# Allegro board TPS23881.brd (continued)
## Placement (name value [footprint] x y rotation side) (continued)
NOREF#927  -  []  73.71 29.35 270 top
NOREF#928  -  []  53.85 71.83 90 top
NOREF#929  -  []  116.54 108.92 90 top
NOREF#930  -  []  146.25 95.33 90 top
NOREF#931  -  []  39.45 60.66 0 top
NOREF#932  -  []  151.89 120.78 90 top
NOREF#933  -  []  110.22 23.8 270 top
NOREF#934  -  []  65.41 52.25 90 top
NOREF#935  -  []  50.52 52.15 0 top
NOREF#936  -  []  31.17 30.98 90 top
NOREF#937  -  []  108.42 53.26 0 top
NOREF#938  -  []  10.13 107.65 0 top
NOREF#939  -  []  73.69 83.92 270 top
NOREF#940  -  []  42.91 36.63 270 top
NOREF#941  -  []  66.57 103.66 90 top
NOREF#942  -  []  109.72 31.37 0 top
NOREF#943  -  []  100.97 17.44 90 top
NOREF#944  -  []  47.07 26.34 0 top
NOREF#945  -  []  17.98 29.07 90 top
NOREF#946  -  []  125.65 133.43 90 top
NOREF#947  -  []  135.81 44.56 90 top
NOREF#948  -  []  35.64 192.23 0 top
NOREF#949  -  []  125.9 32.66 0 top
NOREF#950  -  []  23.06 38.9 90 top
NOREF#951  -  []  45.42 61.93 0 top
NOREF#952  -  []  137.24 45.83 90 top
NOREF#953  -  []  73.79 23.76 270 top
NOREF#954  -  []  116.33 34.43 270 top
NOREF#955  -  []  14.38 107.21 0 top
NOREF#956  -  []  43.81 125.32 270 top
NOREF#957  -  []  95.25 18.41 90 top
NOREF#958  -  []  97.92 36.59 270 top
NOREF#959  -  []  150.88 178.69 90 top
NOREF#960  -  []  118.36 18.41 90 top
NOREF#961  -  []  34.06 192.79 0 top
NOREF#962  -  []  126.44 156.29 0 top
NOREF#963  -  []  137.69 40.28 0 top
NOREF#964  -  []  37.03 17.09 90 top
NOREF#965  -  []  18.19 66.24 0 top
NOREF#966  -  []  75.01 103.17 0 top
NOREF#967  -  []  142.8 99.19 0 top
NOREF#968  -  []  47.27 34.67 0 top
NOREF#969  -  []  134.4 147.19 0 top
NOREF#970  -  []  150.19 120.47 0 top
NOREF#971  -  []  150.14 15.57 0 top
NOREF#972  -  []  100.89 95.17 90 top
NOREF#973  -  []  27.55 194.36 90 top
NOREF#974  -  []  67.03 104.09 0 top
NOREF#975  -  []  21.02 26.54 0 top
NOREF#976  -  []  156.84 176.91 0 top
NOREF#977  -  []  52.18 33.48 90 top
NOREF#978  -  []  153.19 87.88 90 top
NOREF#979  -  []  119.32 109.22 0 top
NOREF#980  -  []  111.02 128.02 0 top
NOREF#981  -  []  91.39 29.07 0 top
NOREF#982  -  []  56.16 78.16 270 top
NOREF#983  -  []  49.82 104.52 0 top
NOREF#984  -  []  135.64 17.4 90 top
NOREF#985  -  []  43.43 62.61 0 top
NOREF#986  -  []  130.63 126.29 0 top
NOREF#987  -  []  60.82 59.64 0 top
NOREF#988  -  []  132.07 54.81 90 top
NOREF#989  -  []  60.82 68.15 0 top
NOREF#990  -  []  148.79 125.81 0 top
NOREF#991  -  []  93.12 106.8 90 top
NOREF#992  -  []  38.28 177.5 90 top
NOREF#993  -  []  19.71 126.87 0 top
NOREF#994  -  []  56.46 149.3 0 top
NOREF#995  -  []  125.34 38.48 0 top
NOREF#996  -  []  43.13 18.72 0 top
NOREF#997  -  []  138.25 35.48 0 top
NOREF#998  -  []  133.6 131.28 270 top
NOREF#999  -  []  133.03 88.39 0 top
NOREF#1000  -  []  140.07 27.3 0 top
NOREF#1001  -  []  129.53 44.02 0 top
NOREF#1002  -  []  110.3 54.06 90 top
NOREF#1003  -  []  13.61 55.74 270 top
NOREF#1004  -  []  84.6 93.31 0 top
NOREF#1005  -  []  60.48 60.96 0 top
NOREF#1006  -  []  36.64 192.23 90 top
NOREF#1007  -  []  120.51 33.78 0 top
NOREF#1008  -  []  73.1 80.06 0 top
NOREF#1009  -  []  75.01 105.11 0 top
NOREF#1010  -  []  136.4 175.03 90 top
NOREF#1011  -  []  151.33 120.47 0 top
NOREF#1012  -  []  61.79 64.6 90 top
NOREF#1013  -  []  28.21 36.91 90 top
NOREF#1014  -  []  138.76 32.31 0 top
NOREF#1015  -  []  151.88 192.28 90 top
NOREF#1016  -  []  144.98 189.03 0 top
NOREF#1017  -  []  135.38 34.81 270 top
NOREF#1018  -  []  132.11 85.64 90 top
NOREF#1019  -  []  52.18 34.09 0 top
NOREF#1020  -  []  93.98 35.89 90 top
NOREF#1021  -  []  49.61 142.7 0 top
NOREF#1022  -  []  59.45 113.3 0 top
NOREF#1023  -  []  7.19 78.16 0 top
NOREF#1024  -  []  153.09 92.76 270 top
NOREF#1025  -  []  100.25 24.54 90 top
NOREF#1026  -  []  133.53 88.39 0 top
NOREF#1027  -  []  46.39 145.41 0 top
NOREF#1028  -  []  119.08 135.2 90 top
NOREF#1029  -  []  126.44 155.88 270 top
NOREF#1030  -  []  149.39 12.68 0 top
NOREF#1031  -  []  120.62 71.07 90 top
NOREF#1032  -  []  33.9 37.72 0 top
NOREF#1033  -  []  15.82 79.98 90 top
NOREF#1034  -  []  77.97 18.41 90 top
NOREF#1035  -  []  132.99 88.14 90 top
NOREF#1036  -  []  18.57 20.47 90 top
NOREF#1037  -  []  140.63 46.1 0 top
NOREF#1038  -  []  56.21 54.56 0 top
NOREF#1039  -  []  71.32 32.12 0 top
NOREF#1040  -  []  146.96 88.64 90 top
NOREF#1041  -  []  51.88 112.08 270 top
NOREF#1042  -  []  9.55 108.86 90 top
NOREF#1043  -  []  60.91 113.3 0 top
NOREF#1044  -  []  11.2 126.39 0 top
NOREF#1045  -  []  51.94 47.65 90 top
NOREF#1046  -  []  133.68 176.45 0 top
NOREF#1047  -  []  134.11 53.07 90 top
NOREF#1048  -  []  49.56 73.46 0 top
NOREF#1049  -  []  101.02 139.88 270 top
NOREF#1050  -  []  93.5 99.51 90 top
NOREF#1051  -  []  135.64 135.08 0 top
NOREF#1052  -  []  11.58 110.74 0 top
NOREF#1053  -  []  86.37 0.56 90 top
NOREF#1054  -  []  55.14 78.16 270 top
NOREF#1055  -  []  147.67 120.79 90 top
NOREF#1056  -  []  32.92 192.79 0 top
NOREF#1057  -  []  136.88 89.97 0 top
NOREF#1058  -  []  40.13 25.62 90 top
NOREF#1059  -  []  74.28 23.8 0 top
NOREF#1060  -  []  73.51 110.57 0 top
NOREF#1061  -  []  113.87 157.78 270 top
NOREF#1062  -  []  89.61 26.15 0 top
NOREF#1063  -  []  59.64 109.74 270 top
NOREF#1064  -  []  53.29 77.85 270 top
NOREF#1065  -  []  38.76 84.99 90 top
NOREF#1066  -  []  51.64 71.83 90 top
NOREF#1067  -  []  75.39 37.17 270 top
NOREF#1068  -  []  47.17 58.52 90 top
NOREF#1069  -  []  67.44 83.78 270 top
NOREF#1070  -  []  147.4 129.49 0 top
NOREF#1071  -  []  140.67 26.11 0 top
NOREF#1072  -  []  138.76 28.71 0 top
NOREF#1073  -  []  113.28 25.62 90 top
NOREF#1074  -  []  83.93 28.83 0 top
NOREF#1075  -  []  52.1 145.06 0 top
NOREF#1076  -  []  96.29 108.48 90 top
NOREF#1077  -  []  105.16 138.46 90 top
NOREF#1078  -  []  58.66 92.9 90 top
NOREF#1079  -  []  129.55 42.24 90 top
NOREF#1080  -  []  48.77 150.5 0 top
NOREF#1081  -  []  83.9 31.93 0 top
NOREF#1082  -  []  10.46 123.83 0 top
NOREF#1083  -  []  80.4 36.63 270 top
NOREF#1084  -  []  85.2 27.56 0 top
NOREF#1085  -  []  139.6 107.7 90 top
NOREF#1086  -  []  120.62 70.28 0 top
NOREF#1087  -  []  123.7 171.41 270 top
NOREF#1088  -  []  138.82 26.17 90 top
NOREF#1089  -  []  123.44 153.29 90 top
NOREF#1090  -  []  55.85 166.7 0 top
NOREF#1091  -  []  56.58 112.99 270 top
NOREF#1092  -  []  90.53 98.86 90 top
NOREF#1093  -  []  55.55 53.14 270 top
NOREF#1094  -  []  71.06 25.98 0 top
NOREF#1095  -  []  45.42 215.26 0 top
NOREF#1096  -  []  18.05 36.4 90 top
NOREF#1097  -  []  94.39 37.52 0 top
NOREF#1098  -  []  102.87 104.24 270 top
NOREF#1099  -  []  92 29.35 270 top
NOREF#1100  -  []  24.31 28.54 90 top
NOREF#1101  -  []  138.91 74.88 90 top
NOREF#1102  -  []  115.82 122.58 90 top
NOREF#1103  -  []  146.05 121.79 270 top
NOREF#1104  -  []  37.36 105.44 0 top
NOREF#1105  -  []  127.69 56.52 0 top
NOREF#1106  -  []  95.52 101.83 90 top
NOREF#1107  -  []  37.07 25.22 0 top
NOREF#1108  -  []  133.48 42.28 90 top
NOREF#1109  -  []  142.82 127.69 0 top
NOREF#1110  -  []  57.34 112.95 270 top
NOREF#1111  -  []  145.16 134.09 270 top
NOREF#1112  -  []  82.31 34.52 270 top
NOREF#1113  -  []  134.37 146.94 0 top
NOREF#1114  -  []  144.98 105.23 0 top
NOREF#1115  -  []  58.99 91.68 0 top
NOREF#1116  -  []  55.4 167.13 0 top
NOREF#1117  -  []  43.43 62.1 90 top
NOREF#1118  -  []  15.52 108.74 0 top
NOREF#1119  -  []  39.99 25.58 90 top
NOREF#1120  -  []  19.76 70.82 0 top
NOREF#1121  -  []  17.98 35.04 90 top
NOREF#1122  -  []  91.94 25.22 0 top
NOREF#1123  -  []  98.73 139.88 270 top
NOREF#1124  -  []  138.76 29.96 0 top
NOREF#1125  -  []  107.9 28.33 270 top
NOREF#1126  -  []  47.93 33.64 90 top
NOREF#1127  -  []  73.65 25.22 0 top
NOREF#1128  -  []  94.51 101.83 0 top
NOREF#1129  -  []  27.04 37.39 0 top
NOREF#1130  -  []  128.92 42.24 90 top
NOREF#1131  -  []  117.73 35.97 90 top
NOREF#1132  -  []  157.77 112.2 90 top
NOREF#1133  -  []  136.89 27.99 0 top
NOREF#1134  -  []  121.62 182.04 0 top
NOREF#1135  -  []  70.94 29.98 270 top
NOREF#1136  -  []  137.11 87.96 90 top
NOREF#1137  -  []  128.98 72.95 270 top
NOREF#1138  -  []  119.39 180.47 90 top
NOREF#1139  -  []  58.88 73.19 270 top
NOREF#1140  -  []  135.17 40.06 90 top
NOREF#1141  -  []  43 65.48 0 top
NOREF#1142  -  []  89.65 28.83 0 top
NOREF#1143  -  []  139.34 40.67 90 top
NOREF#1144  -  []  156.99 9.7 90 top
NOREF#1145  -  []  138.33 42.8 0 top
NOREF#1146  -  []  21.03 21.79 90 top
NOREF#1147  -  []  19.76 71.96 0 top
NOREF#1148  -  []  20.43 39.19 0 top
NOREF#1149  -  []  108.58 155.83 0 top
NOREF#1150  -  []  72.72 53.54 90 top
NOREF#1151  -  []  51.61 102.57 0 top
NOREF#1152  -  []  51.1 104.83 270 top
NOREF#1153  -  []  6.3 84.18 90 top
NOREF#1154  -  []  137.27 45.97 0 top
NOREF#1155  -  []  138.48 89.03 0 top
NOREF#1156  -  []  75.46 106.17 0 top
NOREF#1157  -  []  45.72 60.58 90 top
NOREF#1158  -  []  31.75 12.52 270 top
NOREF#1159  -  []  54.31 148.89 270 top
NOREF#1160  -  []  38.51 101.73 0 top
NOREF#1161  -  []  128.52 173.99 90 top
NOREF#1162  -  []  70.33 141.43 0 top
NOREF#1163  -  []  109.91 35.51 90 top
NOREF#1164  -  []  103.36 51.83 90 top
NOREF#1165  -  []  94.12 99.43 90 top
NOREF#1166  -  []  89.31 108.84 0 top
NOREF#1167  -  []  117.3 35.51 0 top
NOREF#1168  -  []  142.88 70.57 270 top
NOREF#1169  -  []  52.32 33.52 90 top
NOREF#1170  -  []  38.56 36.2 90 top
NOREF#1171  -  []  132.36 56.29 90 top
NOREF#1172  -  []  60.87 69.22 0 top
NOREF#1173  -  []  134.52 56.29 0 top
NOREF#1174  -  []  71.39 33.48 90 top
NOREF#1175  -  []  83.64 51.38 90 top
NOREF#1176  -  []  69.77 151.59 90 top
NOREF#1177  -  []  121.34 44.58 0 top
NOREF#1178  -  []  137.24 102.95 0 top
NOREF#1179  -  []  108.71 12.52 0 top
NOREF#1180  -  []  61.4 91.68 0 top
NOREF#1181  -  []  115.72 43.28 0 top
NOREF#1182  -  []  70.94 29.71 0 top
NOREF#1183  -  []  90.87 99.16 0 top
NOREF#1184  -  []  132.7 56.59 0 top
NOREF#1185  -  []  60.82 64.85 0 top
NOREF#1186  -  []  114.3 -29.84 0 top
NOREF#1187  -  []  11.89 123.39 90 top
NOREF#1188  -  []  124.21 17.44 90 top
NOREF#1189  -  []  128.51 24.18 270 top
NOREF#1190  -  []  47.07 186.64 90 top
NOREF#1191  -  []  89.32 32.28 0 top
NOREF#1192  -  []  45.2 45.67 0 top
NOREF#1193  -  []  53.85 73.46 0 top
NOREF#1194  -  []  21.13 126.44 90 top
NOREF#1195  -  []  84.2 51.08 90 top
NOREF#1196  -  []  20.71 28.18 90 top
NOREF#1197  -  []  19.13 20.78 90 top
NOREF#1198  -  []  150.91 192.53 0 top
NOREF#1199  -  []  62.1 63.12 270 top
NOREF#1200  -  []  85.91 54.61 90 top
NOREF#1201  -  []  57.26 91.53 270 top
NOREF#1202  -  []  63.74 27.61 0 top
NOREF#1203  -  []  135.41 104.52 0 top
NOREF#1204  -  []  85.04 103.68 270 top
NOREF#1205  -  []  141.33 75.85 270 top
NOREF#1206  -  []  102.23 32.16 90 top
NOREF#1207  -  []  124.21 181.74 270 top
NOREF#1208  -  []  1.27 179.83 0 top
NOREF#1209  -  []  115.04 84.53 90 top
NOREF#1210  -  []  120.09 31.7 90 top
NOREF#1211  -  []  68.83 174.08 270 top
NOREF#1212  -  []  46.37 0.56 90 top
NOREF#1213  -  []  55.75 173.86 90 top
NOREF#1214  -  []  140.03 133.78 0 top
NOREF#1215  -  []  98.4 102.16 0 top
NOREF#1216  -  []  151.59 147.65 0 top
NOREF#1217  -  []  83.95 31.62 270 top
NOREF#1218  -  []  29.55 197.56 90 top
NOREF#1219  -  []  67.69 57.4 270 top
NOREF#1220  -  []  142.19 136.32 0 top
NOREF#1221  -  []  38.8 95.97 90 top
NOREF#1222  -  []  46.02 29.35 270 top
NOREF#1223  -  []  49.35 107.24 270 top
NOREF#1224  -  []  45.42 27.47 0 top
NOREF#1225  -  []  145.16 120.68 90 top
NOREF#1226  -  []  65.63 156.54 0 top
NOREF#1227  -  []  142.82 102.95 0 top
NOREF#1228  -  []  137.54 127.61 270 top
NOREF#1229  -  []  147.96 129.79 90 top
NOREF#1230  -  []  60.78 62.56 0 top
NOREF#1231  -  []  12.55 118.82 0 top
NOREF#1232  -  []  131.43 25.96 0 top
NOREF#1233  -  []  123.7 154.27 270 top
NOREF#1234  -  []  19.76 72.82 270 top
NOREF#1235  -  []  75.46 101.85 0 top
NOREF#1236  -  []  150.91 180.09 0 top
NOREF#1237  -  []  52.7 32.42 0 top
NOREF#1238  -  []  26.42 37.35 270 top
NOREF#1239  -  []  115.76 25.58 90 top
NOREF#1240  -  []  127.03 177.52 0 top
NOREF#1241  -  []  51.64 58.24 270 top
NOREF#1242  -  []  66.88 27.42 0 top
NOREF#1243  -  []  61.46 112.98 90 top
NOREF#1244  -  []  61.19 181.53 0 top
NOREF#1245  -  []  27.88 28.61 90 top
NOREF#1246  -  []  64.1 91.07 90 top
NOREF#1247  -  []  47.36 145.16 90 top
NOREF#1248  -  []  126.7 139.62 270 top
NOREF#1249  -  []  16.92 106.58 90 top
NOREF#1250  -  []  99.81 64.65 90 top
NOREF#1251  -  []  65.1 67.49 270 top
NOREF#1252  -  []  92.06 36.27 0 top
NOREF#1253  -  []  132.03 121.97 0 top
NOREF#1254  -  []  61.34 36.06 90 top
NOREF#1255  -  []  134.92 131.62 270 top
NOREF#1256  -  []  50.11 72.14 90 top
NOREF#1257  -  []  36.56 27.3 0 top
NOREF#1258  -  []  40.96 25.58 90 top
NOREF#1259  -  []  67.81 89.52 0 top
NOREF#1260  -  []  130.63 160.1 0 top
NOREF#1261  -  []  146.43 134.09 270 top
NOREF#1262  -  []  138.94 30.33 270 top
NOREF#1263  -  []  126.44 154.61 270 top
NOREF#1264  -  []  129.27 55.42 0 top
NOREF#1265  -  []  18.59 30.34 90 top
NOREF#1266  -  []  107.9 26.43 270 top
NOREF#1267  -  []  146.81 95.63 90 top
NOREF#1268  -  []  131.02 37.58 90 top
NOREF#1269  -  []  136.94 139.83 0 top
NOREF#1270  -  []  125.4 72.31 270 top
NOREF#1271  -  []  95.96 25.62 90 top
NOREF#1272  -  []  30.59 31.75 0 top
NOREF#1273  -  []  17.98 31.61 0 top
NOREF#1274  -  []  63.63 17.44 90 top
NOREF#1275  -  []  131.83 52.95 90 top
NOREF#1276  -  []  136.14 56.29 90 top
NOREF#1277  -  []  113.08 159.46 90 top
NOREF#1278  -  []  57.48 56.97 0 top
NOREF#1279  -  []  60.48 63.12 0 top
NOREF#1280  -  []  73.25 82.5 0 top
NOREF#1281  -  []  148.54 129.49 0 top
NOREF#1282  -  []  57.87 37.2 90 top
NOREF#1283  -  []  142.34 99.62 0 top
NOREF#1284  -  []  60 112.98 90 top
NOREF#1285  -  []  137.67 121.53 90 top
NOREF#1286  -  []  87.96 92.51 270 top
NOREF#1287  -  []  70.94 28.05 0 top
NOREF#1288  -  []  74.14 194.39 90 top
NOREF#1289  -  []  116.23 70.46 270 top
NOREF#1290  -  []  131.9 158.29 270 top
NOREF#1291  -  []  55.7 77.85 270 top
NOREF#1292  -  []  26.56 37.39 270 top
NOREF#1293  -  []  56.26 36.84 270 top
NOREF#1294  -  []  126.19 30.72 0 top
NOREF#1295  -  []  120.56 26.04 0 top
NOREF#1296  -  []  97.52 51.83 90 top
NOREF#1297  -  []  131.32 176.91 90 top
NOREF#1298  -  []  66.84 101.05 270 top
NOREF#1299  -  []  68.83 25.78 90 top
NOREF#1300  -  []  108.62 155.57 0 top
NOREF#1301  -  []  89.61 30.34 0 top
NOREF#1302  -  []  17.98 34.4 0 top
NOREF#1303  -  []  60.73 71.88 0 top
NOREF#1304  -  []  70.85 36.63 270 top
NOREF#1305  -  []  18.02 32.77 0 top
NOREF#1306  -  []  58.99 112.98 90 top
NOREF#1307  -  []  12.22 80.54 0 top
NOREF#1308  -  []  132.97 175.04 90 top
NOREF#1309  -  []  144.83 127.69 270 top
NOREF#1310  -  []  149.17 66.85 270 top
NOREF#1311  -  []  71.32 32.4 270 top
NOREF#1312  -  []  153.09 90.47 270 top
NOREF#1313  -  []  6.93 108.41 90 top
NOREF#1314  -  []  53.2 33.65 90 top
NOREF#1315  -  []  120.65 134.47 270 top
NOREF#1316  -  []  149.66 68.96 0 top
NOREF#1317  -  []  28.63 29.34 0 top
NOREF#1318  -  []  58.48 95.85 270 top
NOREF#1319  -  []  52.55 194.36 90 top
NOREF#1320  -  []  17.98 80 90 top
NOREF#1321  -  []  96.33 95.25 0 top
NOREF#1322  -  []  43.69 17.4 90 top
NOREF#1323  -  []  125.02 51.04 90 top
NOREF#1324  -  []  83.93 28.19 0 top
NOREF#1325  -  []  144.86 181.15 0 top
NOREF#1326  -  []  23.28 28.49 90 top
NOREF#1327  -  []  132.36 56.9 0 top
NOREF#1328  -  []  16.54 79.53 90 top
NOREF#1329  -  []  100.25 26.42 0 top
NOREF#1330  -  []  89.61 32.4 270 top
NOREF#1331  -  []  142.57 122.15 0 top
NOREF#1332  -  []  148.59 193.8 90 top
NOREF#1333  -  []  140.59 50.8 0 top
NOREF#1334  -  []  95.12 109.45 270 top
NOREF#1335  -  []  138.38 177.46 0 top
NOREF#1336  -  []  45.72 63.25 90 top
NOREF#1337  -  []  49.57 26.04 0 top
NOREF#1338  -  []  62.23 112.95 270 top
NOREF#1339  -  []  138.8 34.16 0 top
NOREF#1340  -  []  60.02 72.25 90 top
NOREF#1341  -  []  128.75 42.48 270 top
NOREF#1342  -  []  140.87 150.6 0 top
NOREF#1343  -  []  100.46 94.72 90 top
NOREF#1344  -  []  59.23 73.33 270 top
NOREF#1345  -  []  54.81 109.87 0 top
NOREF#1346  -  []  9.98 109.32 90 top
NOREF#1347  -  []  49.35 108.38 0 top
NOREF#1348  -  []  134.06 146.35 0 top
NOREF#1349  -  []  121.23 76.4 90 top
NOREF#1350  -  []  44.73 47.37 0 top
NOREF#1351  -  []  146.57 109.66 270 top
NOREF#1352  -  []  62.1 59.33 90 top
NOREF#1353  -  []  115.19 17.44 90 top
NOREF#1354  -  []  39.12 35.89 90 top
NOREF#1355  -  []  132.4 25.96 90 top
NOREF#1356  -  []  131.78 94.16 0 top
NOREF#1357  -  []  56.32 112.95 270 top
NOREF#1358  -  []  100.66 18.72 0 top
NOREF#1359  -  []  124.41 42.41 0 top
NOREF#1360  -  []  57.71 170.89 90 top
NOREF#1361  -  []  135.23 87.43 0 top
NOREF#1362  -  []  76.57 25.58 0 top
NOREF#1363  -  []  52.22 143.13 0 top
NOREF#1364  -  []  149.2 71.2 0 top
NOREF#1365  -  []  38.51 93.22 0 top
NOREF#1366  -  []  54.53 56.31 270 top
NOREF#1367  -  []  56.64 75.65 270 top
NOREF#1368  -  []  92.43 109.4 0 top
NOREF#1369  -  []  21.03 20.78 90 top
NOREF#1370  -  []  68.15 82.5 0 top
NOREF#1371  -  []  30.61 28.7 0 top
NOREF#1372  -  []  140.28 45.8 90 top
NOREF#1373  -  []  146.81 112.65 0 top
NOREF#1374  -  []  16.71 108.92 90 top
NOREF#1375  -  []  45.16 45.42 90 top
NOREF#1376  -  []  148.51 127.69 270 top
NOREF#1377  -  []  39.45 66.75 0 top
NOREF#1378  -  []  35.03 31.79 270 top
NOREF#1379  -  []  126.99 41.53 0 top
NOREF#1380  -  []  47.96 141.15 270 top
NOREF#1381  -  []  107.94 27.56 0 top
NOREF#1382  -  []  62.1 65.15 270 top
NOREF#1383  -  []  93.98 23.76 270 top
NOREF#1384  -  []  137.69 103.38 0 top
NOREF#1385  -  []  138.81 121.79 270 top
NOREF#1386  -  []  110.03 70.11 90 top
NOREF#1387  -  []  70.94 28.69 0 top
NOREF#1388  -  []  69.19 83.62 90 top
NOREF#1389  -  []  84.48 109.6 90 top
NOREF#1390  -  []  32.92 193.07 0 top
NOREF#1391  -  []  141.6 149.52 90 top
NOREF#1392  -  []  66.88 27.7 270 top
NOREF#1393  -  []  57.4 23.76 270 top
NOREF#1394  -  []  54.1 55.85 270 top
NOREF#1395  -  []  47.93 28.05 90 top
NOREF#1396  -  []  57.59 112.99 270 top
NOREF#1397  -  []  50.44 53.11 90 top
NOREF#1398  -  []  35.64 17.09 90 top
NOREF#1399  -  []  74.65 53.54 0 top
NOREF#1400  -  []  106.78 154.76 0 top
NOREF#1401  -  []  134.37 144.66 90 top
NOREF#1402  -  []  126.35 37.01 270 top
NOREF#1403  -  []  47.07 28.52 0 top
NOREF#1404  -  []  17.69 34.57 0 top
NOREF#1405  -  []  18.24 79.96 90 top
NOREF#1406  -  []  129.41 65.43 90 top
NOREF#1407  -  []  56.34 76 0 top
NOREF#1408  -  []  89.32 31.65 0 top
NOREF#1409  -  []  122.89 182.04 0 top
NOREF#1410  -  []  98.5 65.2 0 top
NOREF#1411  -  []  152.53 136.14 90 top
NOREF#1412  -  []  150.57 192.84 0 top
NOREF#1413  -  []  109.68 31.23 90 top
NOREF#1414  -  []  143.26 126.26 90 top
NOREF#1415  -  []  150.57 180.39 270 top
NOREF#1416  -  []  36.83 127.86 270 top
NOREF#1417  -  []  63.7 26.71 0 top
NOREF#1418  -  []  73.18 56.03 0 top
NOREF#1419  -  []  71.03 31.65 0 top
NOREF#1420  -  []  140.11 107.7 90 top
NOREF#1421  -  []  82.03 26.85 0 top
NOREF#1422  -  []  91.94 25.22 90 top
NOREF#1423  -  []  110.82 138.25 90 top
NOREF#1424  -  []  38.96 91.64 0 top
NOREF#1425  -  []  125.22 136.55 90 top
NOREF#1426  -  []  54.1 58.25 270 top
NOREF#1427  -  []  75.01 102.03 0 top
NOREF#1428  -  []  126.44 159.56 0 top
NOREF#1429  -  []  123.95 171.45 270 top
NOREF#1430  -  []  65.56 68.2 0 top
NOREF#1431  -  []  134.37 148.21 90 top
NOREF#1432  -  []  85.04 103.68 0 top
NOREF#1433  -  []  63.61 51.58 90 top
NOREF#1434  -  []  111.81 151.76 0 top
NOREF#1435  -  []  143.75 93.52 0 top
NOREF#1436  -  []  149.1 129.79 90 top
NOREF#1437  -  []  84.87 2.26 90 top
NOREF#1438  -  []  57.78 17.4 90 top
NOREF#1439  -  []  131.98 155.45 0 top
NOREF#1440  -  []  154.97 114.31 90 top
NOREF#1441  -  []  19.76 33.74 0 top
NOREF#1442  -  []  133.91 131.62 270 top
NOREF#1443  -  []  150.67 115.57 0 top
NOREF#1444  -  []  134.62 131.28 270 top
NOREF#1445  -  []  134.37 145.8 90 top
NOREF#1446  -  []  55.37 82.63 0 top
NOREF#1447  -  []  68.33 12.52 0 top
NOREF#1448  -  []  74.98 80.06 270 top
NOREF#1449  -  []  134.85 88.09 90 top
NOREF#1450  -  []  140.89 179.37 270 top
NOREF#1451  -  []  134.8 134.7 90 top
NOREF#1452  -  []  115.87 88.14 0 top
NOREF#1453  -  []  100.13 64.59 90 top
NOREF#1454  -  []  19.8 29.46 0 top
NOREF#1455  -  []  98.84 65.91 0 top
NOREF#1456  -  []  136.53 64.52 90 top
NOREF#1457  -  []  54.81 30.47 90 top
NOREF#1458  -  []  45.39 26.42 0 top
NOREF#1459  -  []  46.02 26.99 270 top
NOREF#1460  -  []  137.03 76.07 0 top
NOREF#1461  -  []  102.18 33.92 0 top
NOREF#1462  -  []  114.94 133.99 90 top
NOREF#1463  -  []  47.71 112.08 270 top
NOREF#1464  -  []  18.8 180.59 0 top
NOREF#1465  -  []  75.46 101.6 0 top
NOREF#1466  -  []  137.03 75.06 0 top
NOREF#1467  -  []  124.08 45.92 0 top
NOREF#1468  -  []  61.47 33.9 90 top
NOREF#1469  -  []  58.57 84.25 270 top
NOREF#1470  -  []  70.79 143.89 0 top
NOREF#1471  -  []  56.29 171.32 0 top
NOREF#1472  -  []  47.96 138.86 0 top
NOREF#1473  -  []  49.2 26.78 90 top
NOREF#1474  -  []  89.61 27.7 0 top
NOREF#1475  -  []  131.84 44.63 270 top
NOREF#1476  -  []  65.84 80.42 0 top
NOREF#1477  -  []  141.01 26.42 0 top
NOREF#1478  -  []  65.1 35.1 0 top
NOREF#1479  -  []  60.27 17.09 90 top
NOREF#1480  -  []  73.25 82.5 0 top
NOREF#1481  -  []  127.04 139.32 0 top
NOREF#1482  -  []  149.66 70.1 0 top
NOREF#1483  -  []  62.98 34.52 0 top
NOREF#1484  -  []  108.03 60.04 90 top
NOREF#1485  -  []  62.94 188.16 0 top
NOREF#1486  -  []  156.81 113.65 90 top
NOREF#1487  -  []  106.55 33.52 90 top
NOREF#1488  -  []  81.86 35.51 90 top
NOREF#1489  -  []  140.09 176.41 0 top
NOREF#1490  -  []  107.9 26.15 0 top
NOREF#1491  -  []  152.04 151.89 0 top
NOREF#1492  -  []  60.48 68.45 0 top
NOREF#1493  -  []  113.14 25.58 90 top
NOREF#1494  -  []  12.75 106.12 90 top
NOREF#1495  -  []  76.71 26.15 270 top
NOREF#1496  -  []  138.42 177.32 0 top
NOREF#1497  -  []  28.02 28.65 90 top
NOREF#1498  -  []  149.05 150.32 90 top
NOREF#1499  -  []  38.98 23.8 0 top
NOREF#1500  -  []  28.6 54.14 90 top
NOREF#1501  -  []  54.74 151 0 top
NOREF#1502  -  []  27.06 38.94 90 top
NOREF#1503  -  []  127.23 56.95 270 top
NOREF#1504  -  []  61.04 51.38 90 top
NOREF#1505  -  []  54.61 168.69 90 top
NOREF#1506  -  []  19.38 79.96 90 top
NOREF#1507  -  []  107.94 32.26 0 top
NOREF#1508  -  []  52.96 55.85 270 top
NOREF#1509  -  []  58.29 109.47 270 top
NOREF#1510  -  []  132.7 55.42 0 top
NOREF#1511  -  []  124.28 65.23 0 top
NOREF#1512  -  []  41.72 25.58 0 top
NOREF#1513  -  []  146.13 173.66 270 top
NOREF#1514  -  []  72.14 6.93 90 top
NOREF#1515  -  []  76.33 52.58 270 top
NOREF#1516  -  []  111.66 37.52 0 top
NOREF#1517  -  []  149.68 99.01 90 top
NOREF#1518  -  []  17.3 114.58 90 top
NOREF#1519  -  []  137.24 46.47 90 top
NOREF#1520  -  []  139.78 43.51 90 top
NOREF#1521  -  []  58.74 112.95 270 top
NOREF#1522  -  []  103.45 27.7 270 top
NOREF#1523  -  []  115.42 87.71 90 top
NOREF#1524  -  []  8.38 110.52 90 top
NOREF#1525  -  []  146.13 128.09 90 top
NOREF#1526  -  []  63.27 177.04 0 top
NOREF#1527  -  []  48.41 139.57 0 top
NOREF#1528  -  []  92.02 60.87 270 top
NOREF#1529  -  []  43.32 34.47 270 top
NOREF#1530  -  []  9.86 79.58 90 top
NOREF#1531  -  []  73.1 30.75 270 top
NOREF#1532  -  []  147.57 134.09 270 top
NOREF#1533  -  []  136.73 76.63 0 top
NOREF#1534  -  []  65.2 80.37 0 top
NOREF#1535  -  []  102.22 33.78 0 top
NOREF#1536  -  []  128.02 165.82 270 top
NOREF#1537  -  []  134.62 52.88 0 top
NOREF#1538  -  []  125.09 76.86 90 top
NOREF#1539  -  []  125.34 34.47 270 top
NOREF#1540  -  []  43.43 17.44 90 top
NOREF#1541  -  []  18.82 79.65 0 top
NOREF#1542  -  []  22.94 20.78 90 top
NOREF#1543  -  []  39.9 64.64 0 top
NOREF#1544  -  []  131.27 176.61 0 top
NOREF#1545  -  []  147.8 99.01 0 top
NOREF#1546  -  []  61.93 113.3 270 top
NOREF#1547  -  []  129.62 55.12 0 top
NOREF#1548  -  []  128.73 139.75 0 top
NOREF#1549  -  []  152.55 19.71 0 top
NOREF#1550  -  []  126.95 41.39 0 top
NOREF#1551  -  []  151.52 101.85 270 top
NOREF#1552  -  []  127.97 30.85 90 top
NOREF#1553  -  []  29.5 191.26 0 top
NOREF#1554  -  []  96.22 18.72 0 top
NOREF#1555  -  []  145.43 109.66 270 top
NOREF#1556  -  []  119.08 133.05 0 top
NOREF#1557  -  []  116.48 39.24 90 top
NOREF#1558  -  []  109.68 30.75 0 top
NOREF#1559  -  []  57.33 151.18 270 top
NOREF#1560  -  []  73.14 31.37 0 top
NOREF#1561  -  []  15.31 21.79 90 top
NOREF#1562  -  []  109.91 152.86 90 top
NOREF#1563  -  []  9.44 109.6 90 top
NOREF#1564  -  []  70.94 28.33 270 top
NOREF#1565  -  []  17.13 40.64 0 top
NOREF#1566  -  []  135.15 88.65 0 top
NOREF#1567  -  []  150.91 177.8 0 top
NOREF#1568  -  []  149.17 74.75 270 top
NOREF#1569  -  []  101.93 25.73 90 top
NOREF#1570  -  []  61.49 181.88 90 top
NOREF#1571  -  []  131.09 72.39 90 top
NOREF#1572  -  []  46.89 76.07 0 top
NOREF#1573  -  []  60.01 25.58 90 top
NOREF#1574  -  []  63.58 35.51 0 top
NOREF#1575  -  []  126.24 77.83 270 top
NOREF#1576  -  []  135.27 36.4 90 top
NOREF#1577  -  []  50.44 98.45 0 top
NOREF#1578  -  []  123.77 45.87 90 top
NOREF#1579  -  []  33.35 191.36 90 top
NOREF#1580  -  []  73.79 25.79 270 top
NOREF#1581  -  []  76.89 104.32 270 top
NOREF#1582  -  []  137.04 75.06 90 top
NOREF#1583  -  []  97.47 25.58 0 top
NOREF#1584  -  []  65.13 66.34 0 top
NOREF#1585  -  []  150.6 149.83 0 top
NOREF#1586  -  []  70.33 83.36 270 top
NOREF#1587  -  []  110.86 23.8 0 top
NOREF#1588  -  []  150.14 17.5 270 top
NOREF#1589  -  []  133.46 44.63 0 top
NOREF#1590  -  []  131.04 73.71 270 top
NOREF#1591  -  []  65.1 35.1 270 top
NOREF#1592  -  []  25.4 65.44 0 top
NOREF#1593  -  []  140.59 79.24 90 top
NOREF#1594  -  []  18.29 109.22 90 top
NOREF#1595  -  []  45.8 70.14 270 top
NOREF#1596  -  []  139.55 107.39 0 top
NOREF#1597  -  []  98.42 95.51 90 top
NOREF#1598  -  []  116.2 36.59 270 top
NOREF#1599  -  []  49.15 58.24 270 top
NOREF#1600  -  []  47.36 28.83 0 top
NOREF#1601  -  []  128 54.69 90 top
NOREF#1602  -  []  32.92 190.91 90 top
NOREF#1603  -  []  35.89 37.39 0 top
NOREF#1604  -  []  107.01 38.24 0 top
NOREF#1605  -  []  139.78 40.21 90 top
NOREF#1606  -  []  126.9 155.45 0 top
NOREF#1607  -  []  70.98 28.19 0 top
NOREF#1608  -  []  75.05 18.41 90 top
NOREF#1609  -  []  132.84 54.85 90 top
NOREF#1610  -  []  13.46 106.58 90 top
NOREF#1611  -  []  137.04 76.08 90 top
NOREF#1612  -  []  10.52 72.97 0 top
NOREF#1613  -  []  91.92 102.51 0 top
NOREF#1614  -  []  164.19 74.63 0 top
NOREF#1615  -  []  101.73 109.07 270 top
NOREF#1616  -  []  39.88 108.74 90 top
NOREF#1617  -  []  83.52 31.7 90 top
NOREF#1618  -  []  127.64 73.66 0 top
NOREF#1619  -  []  58.7 166.75 0 top
NOREF#1620  -  []  54.81 31.23 90 top
NOREF#1621  -  []  46 139.57 0 top
NOREF#1622  -  []  52.7 58.29 270 top
NOREF#1623  -  []  87.4 92.2 270 top
NOREF#1624  -  []  75.55 23.8 270 top
NOREF#1625  -  []  124.16 182.04 0 top
NOREF#1626  -  []  111.2 158.32 0 top
NOREF#1627  -  []  151.64 121.75 270 top
NOREF#1628  -  []  92.71 23.76 270 top
NOREF#1629  -  []  11.89 106.12 0 top
NOREF#1630  -  []  17.51 39.55 0 top
NOREF#1631  -  []  123.39 171.75 270 top
NOREF#1632  -  []  66.84 94.45 0 top
NOREF#1633  -  []  49.17 96.52 270 top
NOREF#1634  -  []  134.37 149.22 0 top
NOREF#1635  -  []  132.92 134.7 0 top
NOREF#1636  -  []  137.31 89.51 270 top
NOREF#1637  -  []  88.85 109.27 270 top
NOREF#1638  -  []  146.81 129.79 90 top
NOREF#1639  -  []  17.09 40.78 270 top
NOREF#1640  -  []  30.55 32.5 0 top
NOREF#1641  -  []  104.09 25.73 0 top
NOREF#1642  -  []  36.56 29.21 0 top
NOREF#1643  -  []  62.94 188.16 0 top
NOREF#1644  -  []  56.34 76 270 top
NOREF#1645  -  []  80.26 36.59 270 top
NOREF#1646  -  []  127.18 140.03 90 top
NOREF#1647  -  []  39.99 25.58 0 top
NOREF#1648  -  []  65.75 91.07 90 top
NOREF#1649  -  []  136.22 64.47 90 top
NOREF#1650  -  []  143.66 100.05 270 top
NOREF#1651  -  []  63.74 26.85 0 top
NOREF#1652  -  []  138.76 34.3 0 top
NOREF#1653  -  []  20.71 28.18 0 top
NOREF#1654  -  []  51.64 173.61 0 top
NOREF#1655  -  []  89.14 36.63 270 top
NOREF#1656  -  []  149.43 134.54 0 top
NOREF#1657  -  []  126.61 52.32 0 top
NOREF#1658  -  []  120.51 29.72 0 top
NOREF#1659  -  []  37.8 104.47 0 top
NOREF#1660  -  []  89.61 26.43 270 top
NOREF#1661  -  []  73.1 76.78 0 top
NOREF#1662  -  []  102.22 32.51 0 top
NOREF#1663  -  []  126.23 29.21 0 top
NOREF#1664  -  []  141.29 62.36 0 top
NOREF#1665  -  []  127.48 65.04 0 top
NOREF#1666  -  []  125.72 37.01 0 top
NOREF#1667  -  []  21.65 25.93 90 top
NOREF#1668  -  []  49.83 138.86 270 top
NOREF#1669  -  []  141.48 175.51 0 top
NOREF#1670  -  []  45.67 138.13 0 top
NOREF#1671  -  []  115.39 119.33 90 top
NOREF#1672  -  []  114.91 109.52 0 top
NOREF#1673  -  []  120.22 28.52 0 top
NOREF#1674  -  []  75.97 85.7 270 top
NOREF#1675  -  []  88.85 106.22 270 top
NOREF#1676  -  []  93.5 191.13 0 top
NOREF#1677  -  []  94.59 102.95 0 top
NOREF#1678  -  []  93.07 107.11 0 top
NOREF#1679  -  []  70.33 81.48 0 top
NOREF#1680  -  []  146.3 95.63 90 top
NOREF#1681  -  []  36.56 30.61 0 top
NOREF#1682  -  []  134.87 130.3 90 top
NOREF#1683  -  []  120.51 32.51 0 top
NOREF#1684  -  []  139.37 184.45 270 top
NOREF#1685  -  []  142.49 175.01 90 top
NOREF#1686  -  []  2.03 9.65 0 top
NOREF#1687  -  []  18.02 29.21 0 top
NOREF#1688  -  []  85.48 101.86 90 top
NOREF#1689  -  []  141.17 174.96 0 top
NOREF#1690  -  []  122.38 78.28 270 top
NOREF#1691  -  []  70.94 30.34 0 top
NOREF#1692  -  []  120.75 104.7 0 top
NOREF#1693  -  []  127.58 88.57 270 top
NOREF#1694  -  []  58.09 93.04 0 top
NOREF#1695  -  []  46 71.65 0 top
NOREF#1696  -  []  66.79 176.79 90 top
NOREF#1697  -  []  131.57 177.89 270 top
NOREF#1698  -  []  139.23 139.83 0 top
NOREF#1699  -  []  139.09 140.18 0 top
NOREF#1700  -  []  108.62 153.16 0 top
NOREF#1701  -  []  59.94 109.4 270 top
NOREF#1702  -  []  82.8 101.68 90 top
NOREF#1703  -  []  140.28 45.8 0 top
NOREF#1704  -  []  139.06 31.03 90 top
NOREF#1705  -  []  93.04 190.7 0 top
NOREF#1706  -  []  129.29 24.14 270 top
NOREF#1707  -  []  126.58 49.92 0 top
NOREF#1708  -  []  101.73 63.72 270 top
NOREF#1709  -  []  102.18 29.58 0 top
NOREF#1710  -  []  151.77 101.88 90 top
NOREF#1711  -  []  70.18 108.89 270 top
NOREF#1712  -  []  140.28 50.24 90 top
NOREF#1713  -  []  74.28 23.8 270 top
NOREF#1714  -  []  60.82 63.83 0 top
NOREF#1715  -  []  141.99 26.16 90 top
NOREF#1716  -  []  142.04 73.58 270 top
NOREF#1717  -  []  118.11 17.44 90 top
NOREF#1718  -  []  157.81 36.05 90 top
NOREF#1719  -  []  119.2 154.36 270 top
NOREF#1720  -  []  54.36 168.66 90 top
NOREF#1721  -  []  104.72 138 90 top
NOREF#1722  -  []  21.11 65.44 90 top
NOREF#1723  -  []  128.41 141.66 0 top
NOREF#1724  -  []  22.68 20.82 90 top
NOREF#1725  -  []  47.37 25.78 0 top
NOREF#1726  -  []  93.42 36.2 90 top
NOREF#1727  -  []  18.15 36.57 90 top
NOREF#1728  -  []  69.98 33.52 90 top
NOREF#1729  -  []  68.45 83.78 270 top
NOREF#1730  -  []  47.07 188.26 0 top
NOREF#1731  -  []  148.34 193.84 90 top
NOREF#1732  -  []  148.29 134.54 0 top
NOREF#1733  -  []  91.07 101.09 0 top
NOREF#1734  -  []  118.75 34.48 270 top
NOREF#1735  -  []  39.45 67.61 270 top
NOREF#1736  -  []  60.48 59.94 0 top
NOREF#1737  -  []  137.81 111.93 90 top
NOREF#1738  -  []  74.63 51.28 90 top
NOREF#1739  -  []  124.84 33.9 90 top
NOREF#1740  -  []  34.67 33.52 90 top
NOREF#1741  -  []  83.9 29.58 0 top
NOREF#1742  -  []  115.04 86.54 0 top
NOREF#1743  -  []  136.86 27.85 0 top
NOREF#1744  -  []  46.6 184.31 90 top
NOREF#1745  -  []  52.15 57.23 90 top
NOREF#1746  -  []  85.8 25.73 0 top
NOREF#1747  -  []  152.8 101.34 270 top
NOREF#1748  -  []  156.54 183.69 0 top
NOREF#1749  -  []  38.51 94.36 0 top
NOREF#1750  -  []  107.57 31.51 0 top
NOREF#1751  -  []  34.75 29.98 270 top
NOREF#1752  -  []  122.56 154.28 270 top
NOREF#1753  -  []  140.23 99.82 0 top
NOREF#1754  -  []  138.38 176.7 0 top
NOREF#1755  -  []  143.64 70.61 270 top
NOREF#1756  -  []  144.98 187.88 0 top
NOREF#1757  -  []  48.21 55.8 270 top
NOREF#1758  -  []  151.22 102.19 0 top
NOREF#1759  -  []  72.72 53.54 270 top
NOREF#1760  -  []  84.51 33.29 270 top
NOREF#1761  -  []  138.28 107.39 0 top
NOREF#1762  -  []  57.35 51.38 0 top
NOREF#1763  -  []  83.66 93.31 270 top
NOREF#1764  -  []  37.59 17.4 90 top
NOREF#1765  -  []  61.46 102.16 270 top
NOREF#1766  -  []  7.62 10.29 90 top
NOREF#1767  -  []  131.04 87.96 0 top
NOREF#1768  -  []  74.14 194.39 90 top
NOREF#1769  -  []  134.26 147.47 0 top
NOREF#1770  -  []  67.82 26.29 0 top
NOREF#1771  -  []  64.72 102.08 270 top
NOREF#1772  -  []  128.02 163.55 270 top
NOREF#1773  -  []  138.1 184.45 270 top
NOREF#1774  -  []  131.5 161.98 270 top
NOREF#1775  -  []  6.96 110.95 0 top
NOREF#1776  -  []  138.13 41.71 270 top
NOREF#1777  -  []  102.87 63.72 270 top
NOREF#1778  -  []  -10.06 78.18 0 top
NOREF#1779  -  []  75.69 37.52 270 top
NOREF#1780  -  []  76.89 98.6 270 top
NOREF#1781  -  []  68.58 182.28 90 top
NOREF#1782  -  []  128.91 141.57 90 top
NOREF#1783  -  []  117.35 153.9 270 top
NOREF#1784  -  []  116.48 41.12 0 top
NOREF#1785  -  []  46.2 73.66 0 top
NOREF#1786  -  []  132.66 56.34 0 top
NOREF#1787  -  []  150.24 121.79 270 top
NOREF#1788  -  []  64.52 67.31 270 top
NOREF#1789  -  []  43.8 34.47 0 top
NOREF#1790  -  []  134.37 146.94 90 top
NOREF#1791  -  []  150.91 178.94 0 top
NOREF#1792  -  []  52.74 32.28 0 top
NOREF#1793  -  []  41 90.27 0 top
NOREF#1794  -  []  88.85 108.41 0 top
NOREF#1795  -  []  137.85 89.66 0 top
NOREF#1796  -  []  142.42 120.27 90 top
NOREF#1797  -  []  56.13 23.76 270 top
NOREF#1798  -  []  73.56 79.63 0 top
NOREF#1799  -  []  148.84 130.77 270 top
NOREF#1800  -  []  137.11 86.56 90 top
NOREF#1801  -  []  81.86 35.51 0 top
NOREF#1802  -  []  145.59 120.22 90 top
NOREF#1803  -  []  98.67 34.47 0 top
NOREF#1804  -  []  102.13 34.67 0 top
NOREF#1805  -  []  46.38 146.56 0 top
NOREF#1806  -  []  65.79 29.95 270 top
NOREF#1807  -  []  55.11 112.98 90 top
NOREF#1808  -  []  137.24 105.23 0 top
NOREF#1809  -  []  129.15 24.18 0 top
NOREF#1810  -  []  146.48 113.03 0 top
NOREF#1811  -  []  124.45 41.91 0 top
NOREF#1812  -  []  92.38 102.08 0 top
NOREF#1813  -  []  151.08 68.53 90 top
NOREF#1814  -  []  135.51 131.32 270 top
NOREF#1815  -  []  92.08 23.76 270 top
NOREF#1816  -  []  9.07 76.15 90 top
NOREF#1817  -  []  57.56 82.63 0 top
NOREF#1818  -  []  142.65 135.89 0 top
NOREF#1819  -  []  48.03 74.19 0 top
NOREF#1820  -  []  141.43 107.39 90 top
NOREF#1821  -  []  128.92 36.65 90 top
NOREF#1822  -  []  66.29 85.05 270 top
NOREF#1823  -  []  151.66 91.19 0 top
NOREF#1824  -  []  131.52 155.02 90 top
NOREF#1825  -  []  102.79 30.4 270 top
NOREF#1826  -  []  10.01 79.12 0 top
NOREF#1827  -  []  138.56 17.4 90 top
NOREF#1828  -  []  52.96 33.52 90 top
NOREF#1829  -  []  40.39 102.01 90 top
NOREF#1830  -  []  73.18 54.89 0 top
NOREF#1831  -  []  157 176.91 0 top
NOREF#1832  -  []  16.76 109.22 90 top
NOREF#1833  -  []  86.06 93.54 270 top
NOREF#1834  -  []  155.53 114.01 90 top
NOREF#1835  -  []  55.83 108.24 90 top
NOREF#1836  -  []  40.84 108.28 90 top
NOREF#1837  -  []  124.28 66.37 0 top
NOREF#1838  -  []  86.69 51.42 90 top
NOREF#1839  -  []  49.35 55.8 270 top
NOREF#1840  -  []  73.65 23.8 270 top
NOREF#1841  -  []  38.51 104.01 0 top
NOREF#1842  -  []  39.12 23.76 270 top
NOREF#1843  -  []  68.17 79.96 0 top
NOREF#1844  -  []  21.79 25.97 90 top
NOREF#1845  -  []  146.3 178.79 270 top
NOREF#1846  -  []  27.55 199.66 0 top
NOREF#1847  -  []  120.78 30.65 90 top
NOREF#1848  -  []  134.62 34.81 270 top
NOREF#1849  -  []  62.06 38.75 270 top
NOREF#1850  -  []  128.64 36.65 0 top
NOREF#1851  -  []  124.84 154.28 270 top
NOREF#1852  -  []  43.78 37.95 0 top
NOREF#1853  -  []  124.41 41.77 0 top
NOREF#1854  -  []  118.97 108.92 0 top
NOREF#1855  -  []  9.07 77.29 90 top
NOREF#1856  -  []  100.58 35.97 90 top
NOREF#1857  -  []  110.29 26.68 270 top
NOREF#1858  -  []  53.04 31.48 0 top
NOREF#1859  -  []  64.31 29.35 270 top
NOREF#1860  -  []  148.03 193.5 0 top
NOREF#1861  -  []  63.82 102.12 270 top
NOREF#1862  -  []  138.58 107.73 90 top
NOREF#1863  -  []  54.55 103.92 0 top
NOREF#1864  -  []  108.48 151.64 0 top
NOREF#1865  -  []  50.06 47.65 0 top
NOREF#1866  -  []  120.47 33.29 0 top
NOREF#1867  -  []  31.86 29.84 0 top
NOREF#1868  -  []  119.08 87.71 90 top
NOREF#1869  -  []  102.16 109.52 270 top
NOREF#1870  -  []  55.37 109.56 270 top
NOREF#1871  -  []  46.05 70.18 270 top
NOREF#1872  -  []  82.03 29.21 0 top
NOREF#1873  -  []  61.04 51.38 0 top
NOREF#1874  -  []  152.04 150.75 0 top
NOREF#1875  -  []  28.71 30.42 0 top
NOREF#1876  -  []  70.47 33.48 90 top
NOREF#1877  -  []  41.14 100.28 0 top
NOREF#1878  -  []  53.59 146.22 90 top
NOREF#1879  -  []  110.22 23.8 0 top
NOREF#1880  -  []  22.81 39.87 90 top
NOREF#1881  -  []  133.27 174.7 90 top
NOREF#1882  -  []  140.63 44.58 0 top
NOREF#1883  -  []  80.72 35.51 0 top
NOREF#1884  -  []  19.3 109.22 90 top
NOREF#1885  -  []  134.06 148.67 90 top
NOREF#1886  -  []  118.36 17.4 90 top
NOREF#1887  -  []  128.27 165.86 270 top
NOREF#1888  -  []  119.18 29.35 270 top
NOREF#1889  -  []  134.37 148.72 90 top
NOREF#1890  -  []  46.76 109.86 270 top
NOREF#1891  -  []  73.1 77.65 270 top
NOREF#1892  -  []  144.09 100.51 270 top
NOREF#1893  -  []  49.56 71.83 90 top
NOREF#1894  -  []  151.21 91.9 0 top
NOREF#1895  -  []  99.69 34.48 270 top
NOREF#1896  -  []  46.76 108.99 0 top
NOREF#1897  -  []  54.53 53.14 270 top
NOREF#1898  -  []  136.83 26.8 0 top
NOREF#1899  -  []  137.47 133.88 0 top
NOREF#1900  -  []  37.82 105.87 0 top
NOREF#1901  -  []  70.18 108.89 0 top
NOREF#1902  -  []  126.06 54.43 0 top
NOREF#1903  -  []  97.47 25.58 90 top
NOREF#1904  -  []  17.98 30.62 0 top
NOREF#1905  -  []  134.23 54.94 90 top
NOREF#1906  -  []  109.04 37.39 0 top
NOREF#1907  -  []  134.95 87.96 90 top
NOREF#1908  -  []  107.05 34.09 0 top
NOREF#1909  -  []  149.17 69.65 0 top
NOREF#1910  -  []  60.82 61.8 0 top
NOREF#1911  -  []  70.94 28.97 270 top
NOREF#1912  -  []  56.9 150.72 270 top
NOREF#1913  -  []  128.61 41.91 0 top
NOREF#1914  -  []  114.3 153.7 90 top
NOREF#1915  -  []  138.8 29.21 0 top
NOREF#1916  -  []  131.18 54.81 0 top
NOREF#1917  -  []  111.26 36.27 90 top
NOREF#1918  -  []  55.45 104.5 270 top
NOREF#1919  -  []  88.76 33.48 90 top
NOREF#1920  -  []  127.71 166.17 0 top
NOREF#1921  -  []  39.45 65.07 270 top
NOREF#1922  -  []  53.07 28.83 0 top
NOREF#1923  -  []  83.57 58.12 270 top
NOREF#1924  -  []  149.87 189.45 0 top
NOREF#1925  -  []  146.02 113.46 0 top
NOREF#1926  -  []  91.03 99.91 0 top
NOREF#1927  -  []  102.22 28.83 0 top
NOREF#1928  -  []  69.14 26.34 270 top
NOREF#1929  -  []  60.78 61.54 0 top
NOREF#1930  -  []  55.83 17.09 90 top
NOREF#1931  -  []  74.12 84.38 270 top
NOREF#1932  -  []  144.86 175.95 0 top
NOREF#1933  -  []  119.08 181.43 0 top
NOREF#1934  -  []  151.94 122.1 270 top
NOREF#1935  -  []  129.04 143.54 270 top
NOREF#1936  -  []  129.24 138.1 0 top
NOREF#1937  -  []  47.62 187.95 90 top
NOREF#1938  -  []  67.69 83.82 270 top
NOREF#1939  -  []  140.59 53.34 90 top
NOREF#1940  -  []  56.46 77.81 270 top
NOREF#1941  -  []  57.78 18.41 90 top
NOREF#1942  -  []  146.13 128.09 0 top
NOREF#1943  -  []  73.63 56.46 0 top
NOREF#1944  -  []  139.47 78.23 90 top
NOREF#1945  -  []  134.35 37.01 0 top
NOREF#1946  -  []  30.55 32.5 90 top
NOREF#1947  -  []  98.98 95.35 90 top
NOREF#1948  -  []  41.14 122.81 90 top
NOREF#1949  -  []  141.99 87.5 0 top
NOREF#1950  -  []  61.34 83.95 270 top
NOREF#1951  -  []  63.32 17.09 90 top
NOREF#1952  -  []  70.98 30.48 0 top
NOREF#1953  -  []  31.23 192.35 0 top
NOREF#1954  -  []  22.93 21.79 90 top
NOREF#1955  -  []  82.17 34.48 270 top
NOREF#1956  -  []  12.09 118.39 0 top
NOREF#1957  -  []  2.24 65.1 0 top
NOREF#1958  -  []  116.22 108.97 90 top
NOREF#1959  -  []  140.82 61.65 0 top
NOREF#1960  -  []  42.42 34.43 270 top
NOREF#1961  -  []  144.38 63.24 90 top
NOREF#1962  -  []  83.46 110.11 0 top
NOREF#1963  -  []  126.31 141.91 0 top
NOREF#1964  -  []  125.3 38.34 90 top
NOREF#1965  -  []  55.63 57.28 90 top
NOREF#1966  -  []  131.32 55.38 270 top
NOREF#1967  -  []  55.63 36.84 270 top
NOREF#1968  -  []  89.61 28.97 270 top
NOREF#1969  -  []  81.15 35.97 90 top
NOREF#1970  -  []  140.77 174.55 270 top
NOREF#1971  -  []  118.61 34.52 0 top
NOREF#1972  -  []  138.23 120.22 90 top
NOREF#1973  -  []  121.74 27.7 270 top
NOREF#1974  -  []  85.06 101.55 90 top
NOREF#1975  -  []  125.48 34.43 270 top
NOREF#1976  -  []  66.84 94.45 270 top
NOREF#1977  -  []  102.57 64.06 0 top
NOREF#1978  -  []  11 81.46 0 top
NOREF#1979  -  []  142.65 133.35 0 top
NOREF#1980  -  []  34.42 32.42 0 top
NOREF#1981  -  []  129.08 75.49 270 top
NOREF#1982  -  []  124.45 51.18 0 top
NOREF#1983  -  []  152.04 146.94 0 top
NOREF#1984  -  []  82.5 52.39 90 top
NOREF#1985  -  []  36.75 35.51 90 top
NOREF#1986  -  []  53.07 29.84 0 top
NOREF#1987  -  []  55.12 109.52 270 top
NOREF#1988  -  []  44.83 34.48 270 top
NOREF#1989  -  []  28.6 67.04 270 top
NOREF#1990  -  []  63.12 109.44 270 top
NOREF#1991  -  []  131.11 163.5 270 top
NOREF#1992  -  []  102.49 30.65 90 top
NOREF#1993  -  []  19.13 106.12 90 top
NOREF#1994  -  []  26.15 39.55 0 top
NOREF#1995  -  []  129.69 69.88 90 top
NOREF#1996  -  []  54.85 29.21 0 top
NOREF#1997  -  []  54.23 52.79 270 top
NOREF#1998  -  []  13.03 108 0 top
NOREF#1999  -  []  129.25 42.52 0 top
NOREF#2000  -  []  74.92 23.8 270 top
NOREF#2001  -  []  155.23 114.35 90 top
NOREF#2002  -  []  12.67 80.98 0 top
NOREF#2003  -  []  96.56 96.93 0 top
NOREF#2004  -  []  54.99 52.83 270 top
NOREF#2005  -  []  56.26 173.86 90 top
NOREF#2006  -  []  120.47 28.33 0 top
NOREF#2007  -  []  137.47 133.88 90 top
NOREF#2008  -  []  108.06 36.63 0 top
NOREF#2009  -  []  147.29 65.99 0 top
NOREF#2010  -  []  140.03 79.55 0 top
NOREF#2011  -  []  147.41 121.77 270 top
NOREF#2012  -  []  53.92 51.51 0 top
NOREF#2013  -  []  135.25 175.03 90 top
NOREF#2014  -  []  135.43 49.01 90 top
NOREF#2015  -  []  34.04 33.52 90 top
NOREF#2016  -  []  42.71 93.12 0 top
NOREF#2017  -  []  157 177.93 0 top
NOREF#2018  -  []  133.25 126.87 0 top
NOREF#2019  -  []  97.87 138 0 top
NOREF#2020  -  []  124.66 131.39 0 top
NOREF#2021  -  []  47.36 32.51 0 top
NOREF#2022  -  []  63.4 188.59 0 top
NOREF#2023  -  []  34.75 31.48 0 top
NOREF#2024  -  []  164.64 75.06 0 top
NOREF#2025  -  []  128.79 64.9 0 top
NOREF#2026  -  []  63.68 173.41 270 top
NOREF#2027  -  []  126.47 32.17 270 top
NOREF#2028  -  []  142.09 98.63 0 top
NOREF#2029  -  []  140.07 27.94 0 top
NOREF#2030  -  []  44.86 45.36 90 top
NOREF#2031  -  []  40.39 100.86 90 top
NOREF#2032  -  []  39.45 108.28 90 top
NOREF#2033  -  []  110.9 153.16 0 top
NOREF#2034  -  []  136.22 77.93 90 top
NOREF#2035  -  []  133.72 34.85 0 top
NOREF#2036  -  []  36.2 17.4 90 top
NOREF#2037  -  []  107.05 38.1 0 top
NOREF#2038  -  []  110.03 70.11 90 top
NOREF#2039  -  []  76.15 37.2 90 top
NOREF#2040  -  []  140.28 53.29 90 top
NOREF#2041  -  []  147.72 122.11 270 top
NOREF#2042  -  []  68.59 89.52 90 top
NOREF#2043  -  []  107.94 26.29 0 top
NOREF#2044  -  []  138.89 107.39 90 top
NOREF#2045  -  []  72.47 37.39 0 top
NOREF#2046  -  []  74.19 53.11 0 top
NOREF#2047  -  []  123.9 18.72 0 top
NOREF#2048  -  []  106.37 0.56 90 top
NOREF#2049  -  []  82.45 53.98 0 top
NOREF#2050  -  []  150.88 191.64 0 top
NOREF#2051  -  []  12.32 106.58 90 top
NOREF#2052  -  []  135.43 48.37 90 top
NOREF#2053  -  []  127.51 54.72 90 top
NOREF#2054  -  []  135.08 53.31 0 top
NOREF#2055  -  []  35.33 192.79 0 top
NOREF#2056  -  []  126.61 50.67 0 top
NOREF#2057  -  []  69.6 82.91 270 top
NOREF#2058  -  []  142.65 134.49 0 top
NOREF#2059  -  []  137.26 25.37 90 top
NOREF#2060  -  []  57.23 17.09 90 top
NOREF#2061  -  []  96.22 17.09 90 top
NOREF#2062  -  []  120.52 171.45 270 top
NOREF#2063  -  []  46.3 71.7 90 top
NOREF#2064  -  []  139.93 99.77 90 top
NOREF#2065  -  []  83.52 56.79 0 top
NOREF#2066  -  []  51.55 33.48 0 top
NOREF#2067  -  []  134.85 88.09 0 top
NOREF#2068  -  []  49.35 77.9 270 top
NOREF#2069  -  []  98.64 37.95 0 top
NOREF#2070  -  []  61.84 68.96 90 top
NOREF#2071  -  []  54.86 168.66 90 top
NOREF#2072  -  []  68.58 174.11 90 top
NOREF#2073  -  []  125.3 38.62 0 top
NOREF#2074  -  []  91.39 27.17 0 top
NOREF#2075  -  []  129.69 163.07 0 top
NOREF#2076  -  []  55.24 52.79 270 top
NOREF#2077  -  []  54.61 35.97 90 top
NOREF#2078  -  []  127.53 65.43 0 top
NOREF#2079  -  []  56.63 23.8 0 top
NOREF#2080  -  []  61.59 102.12 270 top
NOREF#2081  -  []  89.61 31.48 0 top
NOREF#2082  -  []  48.87 0.16 0 top
NOREF#2083  -  []  55.83 171.75 0 top
NOREF#2084  -  []  120.88 44.15 90 top
NOREF#2085  -  []  146.86 191.19 270 top
NOREF#2086  -  []  140.24 99.83 90 top
NOREF#2087  -  []  16.71 108.92 0 top
NOREF#2088  -  []  66.33 97.75 0 top
NOREF#2089  -  []  50.42 76.07 270 top
NOREF#2090  -  []  57.56 84.25 270 top
NOREF#2091  -  []  19.63 108.79 90 top
NOREF#2092  -  []  122.72 26.04 0 top
NOREF#2093  -  []  79.73 109.3 0 top
NOREF#2094  -  []  133.65 165.3 90 top
NOREF#2095  -  []  15.39 81.41 0 top
NOREF#2096  -  []  93.02 100.18 0 top
NOREF#2097  -  []  124.46 181.7 270 top
NOREF#2098  -  []  102.16 104.7 270 top
NOREF#2099  -  []  3.53 85.29 0 top
NOREF#2100  -  []  34.53 33.48 0 top
NOREF#2101  -  []  133.34 165.36 90 top
NOREF#2102  -  []  27.93 37.52 0 top
NOREF#2103  -  []  63.12 109.43 90 top
NOREF#2104  -  []  58.04 72.14 90 top
NOREF#2105  -  []  142.06 178.49 270 top
NOREF#2106  -  []  144.09 18.72 0 top
NOREF#2107  -  []  43.13 62.66 270 top
NOREF#2108  -  []  45.42 29.07 0 top
NOREF#2109  -  []  118.75 153.92 270 top
NOREF#2110  -  []  42.75 25.62 90 top
NOREF#2111  -  []  29.32 29.65 90 top
NOREF#2112  -  []  59.13 102.08 270 top
NOREF#2113  -  []  143.56 122.1 270 top
NOREF#2114  -  []  56.57 112.98 90 top
NOREF#2115  -  []  137.39 88.82 0 top
NOREF#2116  -  []  83.52 18.72 270 top
NOREF#2117  -  []  57.91 95.71 0 top
NOREF#2118  -  []  142.7 60.78 90 top
NOREF#2119  -  []  122.94 181.74 270 top
NOREF#2120  -  []  124.28 70.43 90 top
NOREF#2121  -  []  131.78 92.28 90 top
NOREF#2122  -  []  134.81 47.49 0 top
NOREF#2123  -  []  28.69 37.52 0 top
NOREF#2124  -  []  48.46 151.05 0 top
NOREF#2125  -  []  36.53 26.4 0 top
NOREF#2126  -  []  71.86 82.5 0 top
NOREF#2127  -  []  18.02 31.75 0 top
NOREF#2128  -  []  76.89 102.29 270 top
NOREF#2129  -  []  144.22 98.76 90 top
NOREF#2130  -  []  69.88 80.39 0 top
NOREF#2131  -  []  114.88 18.72 0 top
NOREF#2132  -  []  91.26 40.18 0 top
NOREF#2133  -  []  127.99 65.86 0 top
NOREF#2134  -  []  -8.18 76.91 90 top
NOREF#2135  -  []  115.04 85.39 0 top
NOREF#2136  -  []  139.37 29.07 90 top
NOREF#2137  -  []  140.28 47.19 0 top
NOREF#2138  -  []  139.12 128.07 270 top
NOREF#2139  -  []  128.96 74.22 270 top
NOREF#2140  -  []  137.24 45.2 0 top
NOREF#2141  -  []  34.75 30.62 270 top
NOREF#2142  -  []  153.3 100.96 0 top
NOREF#2143  -  []  65.91 31.58 270 top
NOREF#2144  -  []  63.74 34.52 0 top
NOREF#2145  -  []  66.88 100.15 0 top
NOREF#2146  -  []  139.78 180.1 0 top
NOREF#2147  -  []  145.75 173.69 270 top
NOREF#2148  -  []  133.4 84.3 0 top
NOREF#2149  -  []  132.33 165.35 0 top
NOREF#2150  -  []  60.66 109.74 270 top
NOREF#2151  -  []  67.11 188.16 90 top
NOREF#2152  -  []  82.75 51.42 90 top
NOREF#2153  -  []  38.48 84.99 90 top
NOREF#2154  -  []  53.21 72.14 90 top
NOREF#2155  -  []  112.27 23.76 270 top
NOREF#2156  -  []  73.1 75.64 0 top
NOREF#2157  -  []  128.41 141.66 270 top
NOREF#2158  -  []  153.47 139.65 90 top
NOREF#2159  -  []  79.63 36.59 270 top
NOREF#2160  -  []  142.57 62.05 90 top
NOREF#2161  -  []  83.03 100.63 0 top
NOREF#2162  -  []  34.46 31.65 0 top
NOREF#2163  -  []  118.24 173.61 90 top
NOREF#2164  -  []  127.53 66.57 0 top
NOREF#2165  -  []  135.67 89.41 90 top
NOREF#2166  -  []  100.6 34.52 270 top
NOREF#2167  -  []  49.66 57.23 90 top
NOREF#2168  -  []  6.97 108.66 0 top
NOREF#2169  -  []  17.73 115.04 90 top
NOREF#2170  -  []  60.48 65.15 0 top
NOREF#2171  -  []  117.93 174.17 270 top
NOREF#2172  -  []  56.57 72.17 90 top
NOREF#2173  -  []  18.15 39.55 270 top
NOREF#2174  -  []  99.56 34.52 0 top
NOREF#2175  -  []  112.98 36.23 90 top
NOREF#2176  -  []  75.01 104.32 0 top
NOREF#2177  -  []  6.12 67.04 270 top
NOREF#2178  -  []  126.23 32.64 0 top
NOREF#2179  -  []  122.12 74.32 90 top
NOREF#2180  -  []  82.45 105.19 90 top
NOREF#2181  -  []  140.64 184.45 270 top
NOREF#2182  -  []  108.42 55.06 0 top
NOREF#2183  -  []  53.75 78.16 270 top
NOREF#2184  -  []  -10.06 76.91 0 top
NOREF#2185  -  []  28.88 127.3 270 top
NOREF#2186  -  []  98.69 36.02 90 top
NOREF#2187  -  []  54.74 150.5 90 top
NOREF#2188  -  []  76.4 37.17 270 top
NOREF#2189  -  []  30.89 192.66 270 top
NOREF#2190  -  []  122.56 171.41 270 top
NOREF#2191  -  []  58.05 92.9 0 top
NOREF#2192  -  []  20.09 76.1 0 top
NOREF#2193  -  []  47.73 56.79 0 top
NOREF#2194  -  []  82.19 105.16 90 top
NOREF#2195  -  []  88.72 37.58 90 top
NOREF#2196  -  []  65.61 91.11 90 top
NOREF#2197  -  []  48.64 56.26 270 top
NOREF#2198  -  []  65.56 34.67 0 top
NOREF#2199  -  []  50.79 104.27 90 top
NOREF#2200  -  []  152.63 87.58 0 top
NOREF#2201  -  []  89.65 29.84 0 top
NOREF#2202  -  []  152.91 140.96 90 top
NOREF#2203  -  []  31.83 29.98 0 top
NOREF#2204  -  []  50.85 91.25 0 top
NOREF#2205  -  []  132.05 73.71 270 top
NOREF#2206  -  []  102.44 102.82 0 top
NOREF#2207  -  []  57.91 75.68 90 top
NOREF#2208  -  []  60.02 91.64 270 top
NOREF#2209  -  []  36.53 29.07 0 top
NOREF#2210  -  []  51 151.18 0 top
NOREF#2211  -  []  129.78 24.18 270 top
NOREF#2212  -  []  124.74 66.8 0 top
NOREF#2213  -  []  0 0 0 top
NOREF#2214  -  []  109.21 155.28 0 top
NOREF#2215  -  []  57.78 58.25 270 top
NOREF#2216  -  []  77.53 25.58 0 top
NOREF#2217  -  []  47.45 143.56 0 top
NOREF#2218  -  []  39.9 62.23 0 top
NOREF#2219  -  []  94.55 102.08 0 top
NOREF#2220  -  []  44.86 45.36 0 top
NOREF#2221  -  []  145.31 180.72 0 top
NOREF#2222  -  []  67.26 56.95 270 top
NOREF#2223  -  []  80.19 108.46 0 top
NOREF#2224  -  []  26.15 38.94 90 top
NOREF#2225  -  []  52.65 73.46 0 top
NOREF#2226  -  []  93.84 23.8 270 top
NOREF#2227  -  []  73.71 26.68 270 top
NOREF#2228  -  []  119.08 87.71 0 top
NOREF#2229  -  []  25.07 179.07 0 top
